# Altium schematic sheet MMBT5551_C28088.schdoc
size 127 x 101 mm
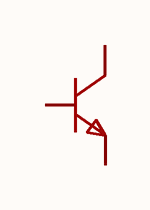
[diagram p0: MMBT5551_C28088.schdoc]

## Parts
Q?  mmbt5551(range:100-200)  [SOT-23-3_L2.9-W1.3-P1.90-LS2.4-BR]  (value not drawn)

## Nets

Not connected (* = marked no-connect by the designer): Q? 1(B) 2(E) 3(C)

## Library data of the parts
Q? = mmbt5551(range:100-200): 晶体管类型:NPN;集电极电流(Ic):600mA;集射极击穿电压(Vceo):160V;耗散功率(Pd):300mW;直流电流增益(hFE):100;; Manufacturer: CJ(江苏长电/长晶); Symbol: MMBT5551_C28088; AddInBom: yes; ModelId: c62791f0466c4ae2a892c056b845b0ca; ModelName: SOT-23-3P_L2.9-W1.3-H1.0-LS2.4-P0.95; ModelTransform: 98.425,114.173,0,180,0,0,0.0005,-0.0005,0; type: NPN; Current - Collector(Ic): 600mA; Collector - Emitter Voltage VCEO: 160V; Pd - Power Dissipation: 300mW; DC Current Gain: 100; Transition frequency(fT): 300MHz; Current - Collector Cutoff: 50nA; Vce Saturation(VCE(sat)): 200mV; Emitter-Base Voltage(Vebo): 6V; Number: 1个NPN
